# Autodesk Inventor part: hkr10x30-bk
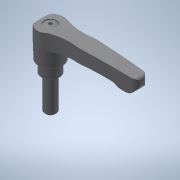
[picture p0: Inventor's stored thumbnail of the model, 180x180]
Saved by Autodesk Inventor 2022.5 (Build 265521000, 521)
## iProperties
Created: 2017-09
Part Number: hkr10x30-bk
Material: 一般
Document SubType Name: Modeling
Designer: imaocorp
Density: 1 g/cm^3
Appearance: 既定
Author: imaocorp
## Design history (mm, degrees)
node "hkr10x30-bk.x_t1"
node "hkr10x30-bk"
node "Base1"
